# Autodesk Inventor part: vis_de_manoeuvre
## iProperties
Shininess: 64.0
Length Units: 11269
Angle Units: 11279
Time Units: 11290
Mass Units: 11283
Length Display Precision: 3
Angle Display Precision: 2
Compacted: True
Part Number: vis_de_manoeuvre
Document SubType Name: Modeling
Created: 2004-05
Material: Par défaut
Designer: David
Density: 0.0
Volumn: 0.0
Area: 0.0
PropertySet Name: Model Information
Control State: 0
Master: False
Checked Out: False
Author: David
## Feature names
1. Révolution1 [Revolution]
2. Chanfrein2 [Chamfer]
3. Chanfrein3 [Chamfer]
4. Extrusion1
5. Hélicoïde1
